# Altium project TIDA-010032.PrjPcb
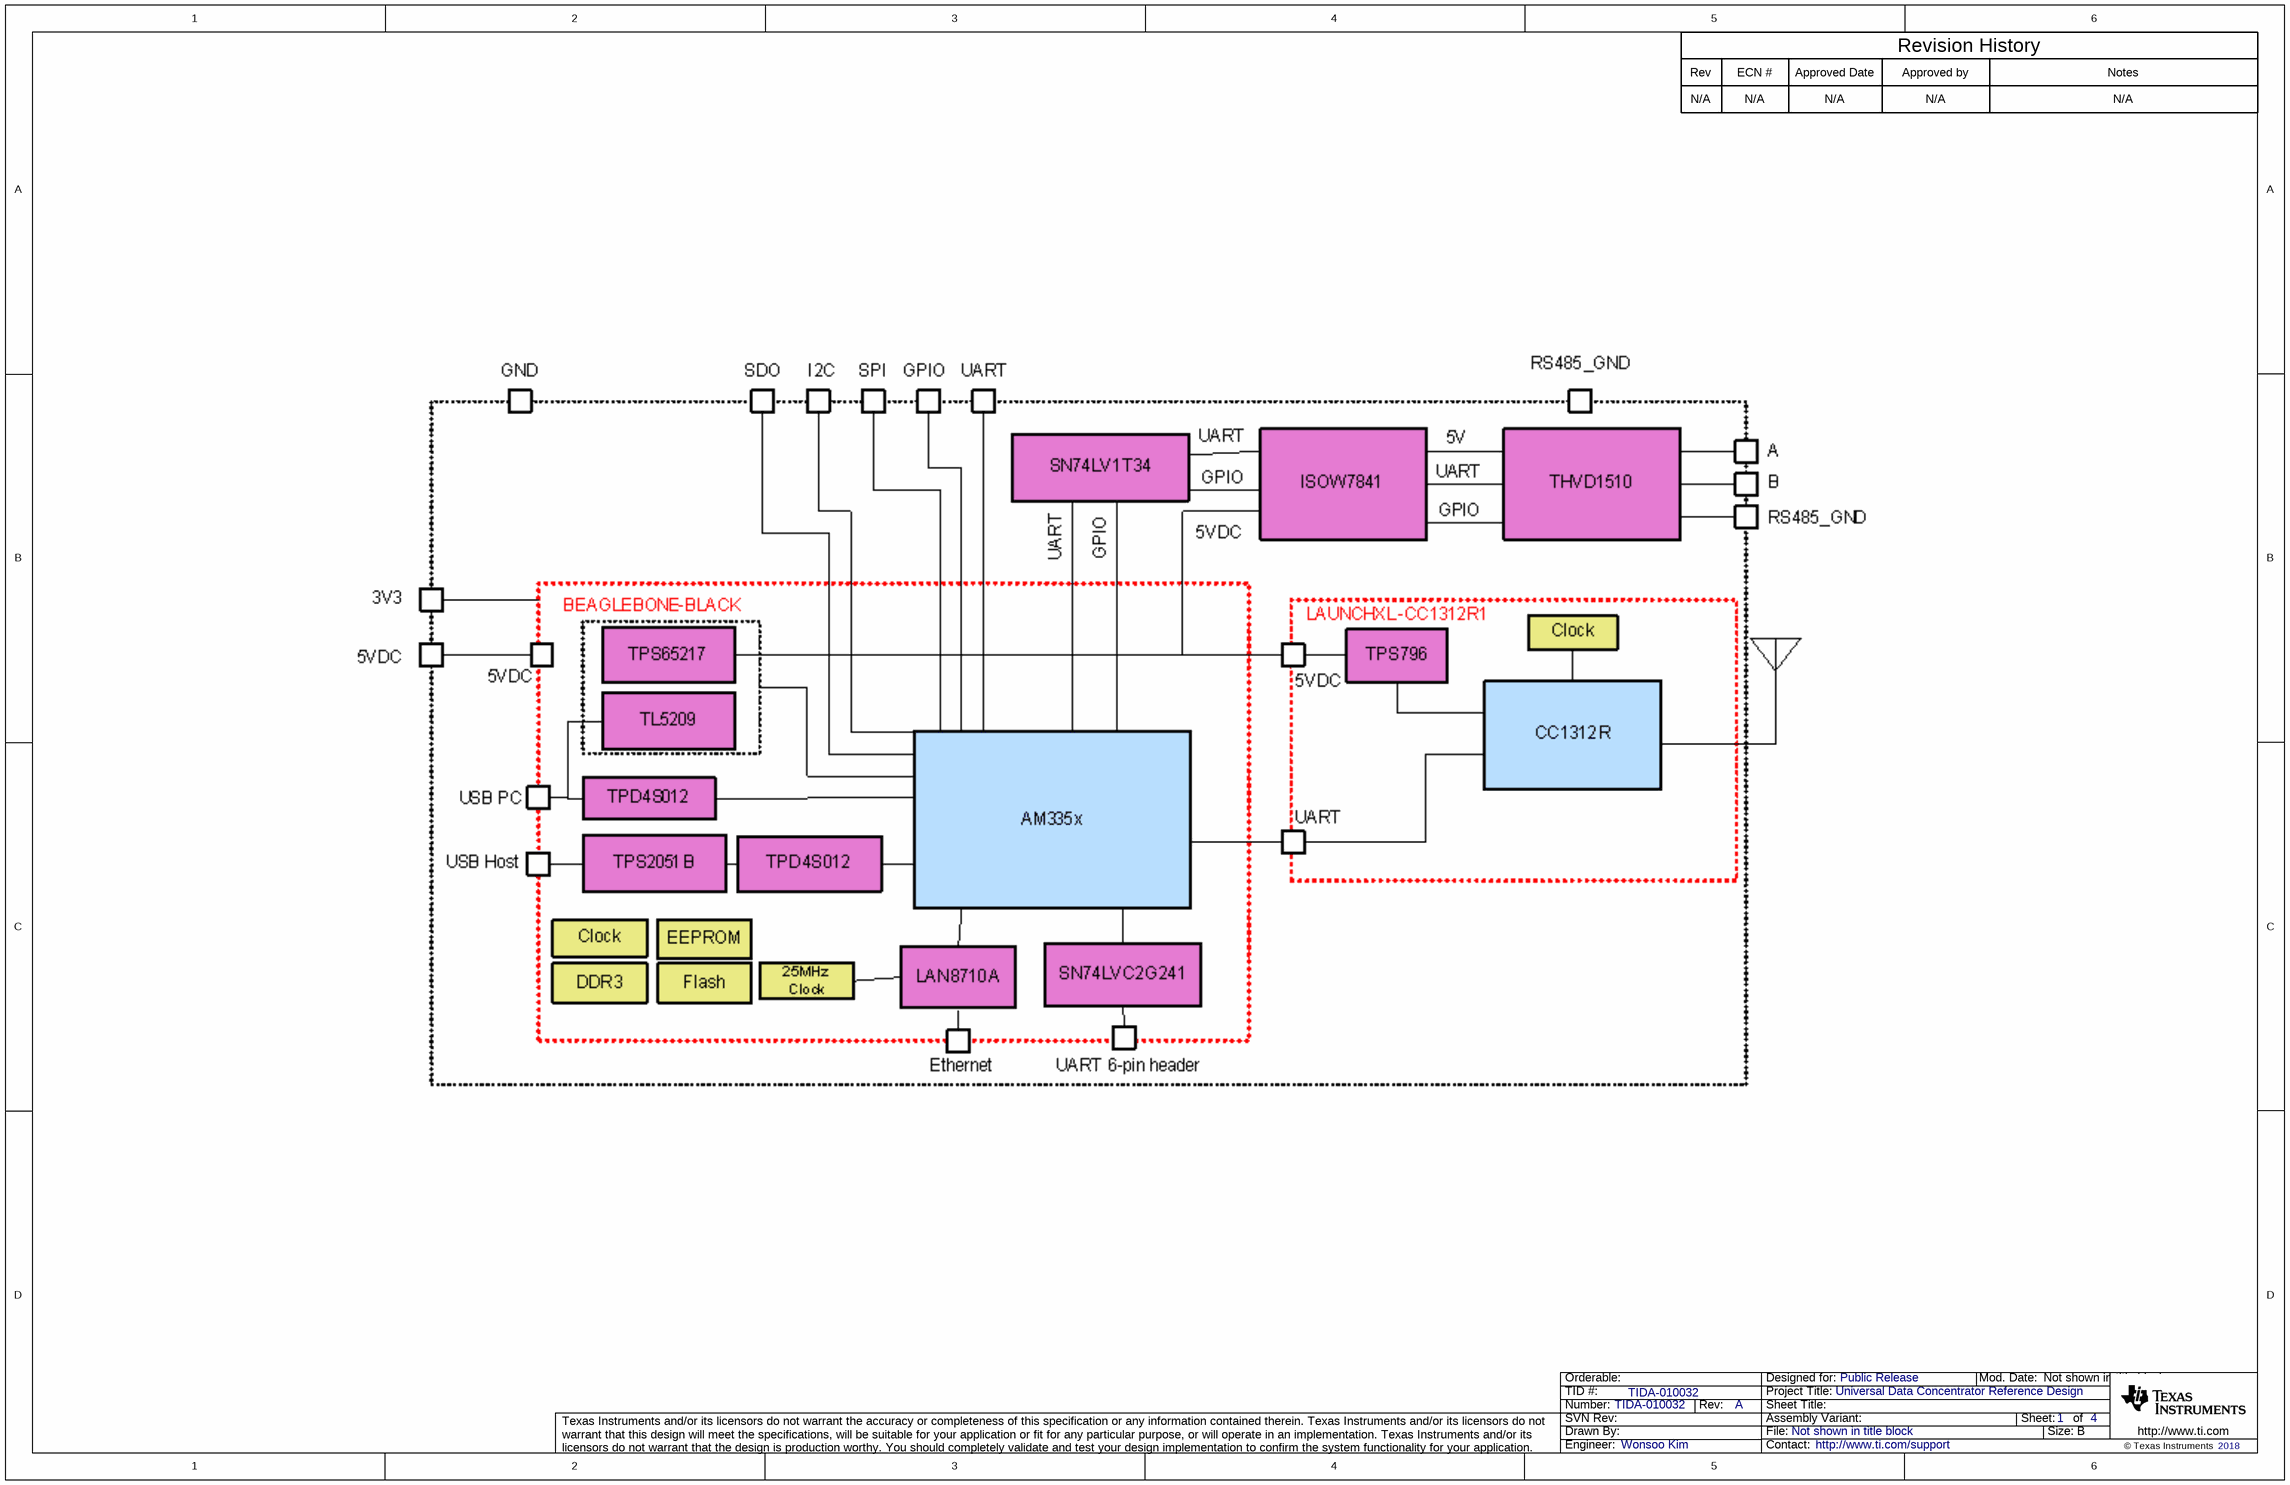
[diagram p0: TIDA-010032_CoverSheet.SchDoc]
CopyrightYear: 2018; PCB_Layout: Wonsoo Kim; PCB_Rev: A; PRJ_Customer: Public Release; PRJ_Engineer: Wonsoo Kim; PRJ_Number: TIDA-010032; PRJ_Title: Universal Data Concentrator Reference Design; SCH_Rev: A; TechSupport: http://www.ti.com/support; TID: TIDA-010032
4 sheets, 62 parts. Net scope: flat (ports and power ports of the same name join across sheets).
Board file: TIDA-010032_PCB.PcbDoc
Sheets:
  TIDA-010032_CoverSheet.SchDoc
  TIDA-010032_1.SchDoc
  TIDA-010032_2.SchDoc
  TIDA-010032_EVM_Hardware.SchDoc

## Sheet TIDA-010032_CoverSheet.SchDoc
size 431 x 279 mm; Date: Not shown in title block; ApprovedBy: Not shown in title block; CheckedBy: Not shown in title block; Author: Not shown in title block; CompanyName: Not shown in title block; Engineer: Not shown in title block; Organization: Not shown in title block; Address1: Not shown in title block; Address2: Not shown in title block; Address3: Not shown in title block; Address4: Not shown in title block; DocumentNumber: 1; Revision: Use project parameter SCH_Rev; SheetNumber: 1; SheetTotal: 4; PageSetup: Record=PageOptions¦CenterHorizontal=True¦CenterVertical=True¦PrintScale=1.00¦XCorrection=1.00¦YCorrection=1.00¦PrintKind=0¦BorderSize=5000000¦LeftOffset=0¦BottomOffset=0¦Orientation=2¦PaperLength=1000¦PaperWidth=1000¦Scale=100¦PaperSource=15¦PrintQuality=600¦MediaType=1¦DitherType=10¦PaperKind=Letter¦PrintScaleMode=1

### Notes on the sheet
- Rev
- N/A
- ECN #
- Approved Date
- Approved by
- Revision History
- Notes

## Sheet TIDA-010032_1.SchDoc
size 431 x 279 mm; Date: Not shown in title block; ApprovedBy: Not shown in title block; CheckedBy: Not shown in title block; Author: Not shown in title block; CompanyName: Not shown in title block; Engineer: Not shown in title block; Organization: Not shown in title block; Address1: Not shown in title block; Address2: Not shown in title block; Address3: Not shown in title block; Address4: Not shown in title block; DocumentNumber: 1; Revision: Use project parameter SCH_Rev; SheetNumber: 2; SheetTotal: 4; PageSetup: Record=PageOptions¦CenterHorizontal=True¦CenterVertical=True¦PrintScale=0.62¦XCorrection=1.00¦YCorrection=1.00¦PrintKind=0¦BorderSize=5000000¦LeftOffset=0¦BottomOffset=0¦Orientation=2¦PaperLength=1000¦PaperWidth=1000¦Scale=100¦PaperSource=15¦PrintQuality=600¦MediaType=1¦DitherType=10¦PrintScaleMode=1¦PaperKind=Letter
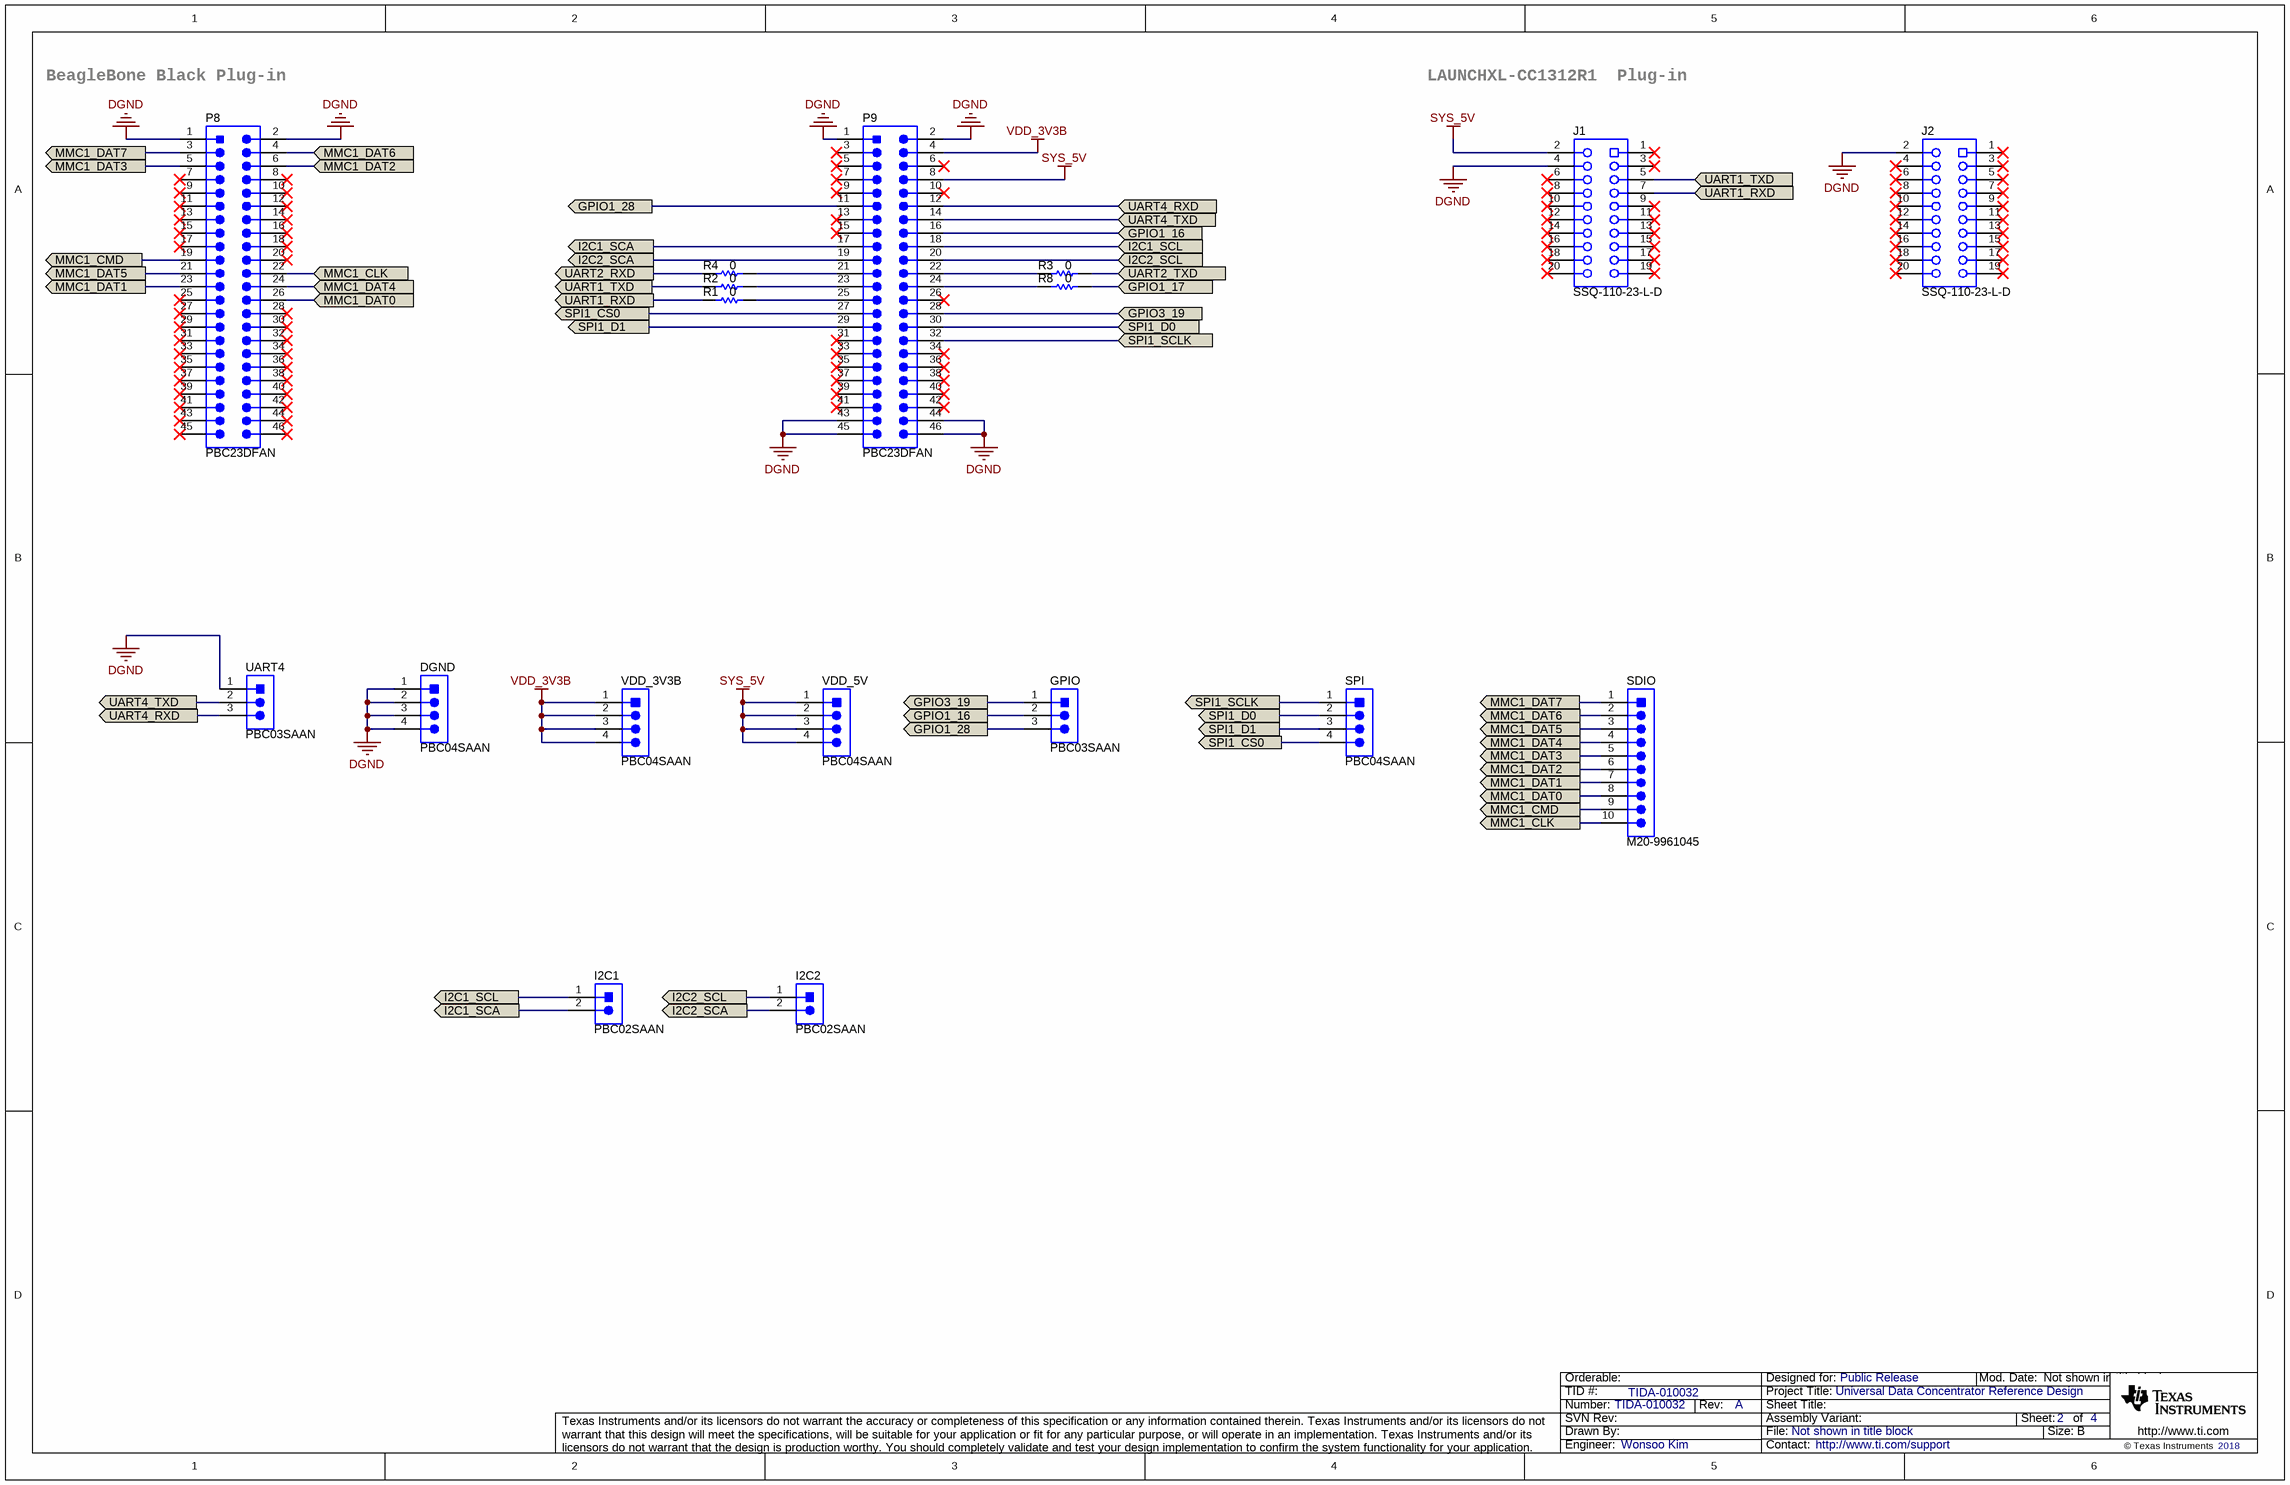
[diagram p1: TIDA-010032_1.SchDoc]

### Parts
DGND  PBC04SAAN  [Sullins_xxC04SAAN]
GPIO  PBC03SAAN  [PBC03SAAN]
I2C1  PBC02SAAN  [Sullins_PBC02SAAN]
I2C2  PBC02SAAN  [Sullins_PBC02SAAN]
J1  SSQ-110-23-L-D  [Samtec_SSQ-110-23-x-D]
J2  SSQ-110-23-L-D  [Samtec_SSQ-110-23-x-D]
P8  PBC23DFAN  [Sullins_PBC23DFAN]
P9  PBC23DFAN  [Sullins_PBC23DFAN]
R1  value 0  [0603]  (hidden comment: ERJ-3GEY0R00V)
R2  value 0  [0603]  (hidden comment: ERJ-3GEY0R00V)
R3  value 0  [0603]  (hidden comment: ERJ-3GEY0R00V)
R4  value 0  [0603]  (hidden comment: ERJ-3GEY0R00V)
R8  value 0  [0603]  (hidden comment: ERJ-3GEY0R00V)
SDIO  M20-9961045  [Harwin_M20-9961045]
SPI  PBC04SAAN  [Sullins_xxC04SAAN]
UART4  PBC03SAAN  [PBC03SAAN]
VDD_3V3B  PBC04SAAN  [Sullins_xxC04SAAN]
VDD_5V  PBC04SAAN  [Sullins_xxC04SAAN]

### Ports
GPIO1_16, GPIO1_17, GPIO1_28, GPIO3_19, I2C1_SCA, I2C1_SCL, I2C2_SCA, I2C2_SCL, MMC1_CLK, MMC1_CMD, MMC1_DAT0, MMC1_DAT1, MMC1_DAT2, MMC1_DAT3, MMC1_DAT4, MMC1_DAT5, MMC1_DAT6, MMC1_DAT7, SPI1_CS0, SPI1_D0, SPI1_D1, SPI1_SCLK, UART1_RXD, UART1_TXD, UART2_RXD, UART2_TXD, UART4_RXD, UART4_TXD

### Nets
DGND: DGND.1 DGND.2 DGND.3 DGND.4 J1.4 J2.2 P8.1 P8.2 P9.1 P9.2 P9.43 P9.44 P9.45 P9.46 UART4.1
SYS_5V: J1.2 P9.8 VDD_5V.1 VDD_5V.2 VDD_5V.3 VDD_5V.4
VDD_3V3B: P9.4 VDD_3V3B.1 VDD_3V3B.2 VDD_3V3B.3 VDD_3V3B.4
GPIO1_16: GPIO.2 P9.16 ; port GPIO1_16
GPIO1_17: R8.2 ; port GPIO1_17
GPIO1_28: GPIO.3 P9.11 ; port GPIO1_28
GPIO3_19: GPIO.1 P9.28 ; port GPIO3_19
I2C1_SCA: I2C1.2 P9.17 ; port I2C1_SCA
I2C1_SCL: I2C1.1 P9.18 ; port I2C1_SCL
I2C2_SCA: I2C2.2 P9.19 ; port I2C2_SCA
I2C2_SCL: I2C2.1 P9.20 ; port I2C2_SCL
MMC1_CLK: P8.22 SDIO.10 ; port MMC1_CLK
MMC1_CMD: P8.19 SDIO.9 ; port MMC1_CMD
MMC1_DAT0: P8.26 SDIO.8 ; port MMC1_DAT0
MMC1_DAT1: P8.23 SDIO.7 ; port MMC1_DAT1
MMC1_DAT2: P8.6 SDIO.6 ; port MMC1_DAT2
MMC1_DAT3: P8.5 SDIO.5 ; port MMC1_DAT3
MMC1_DAT4: P8.24 SDIO.4 ; port MMC1_DAT4
MMC1_DAT5: P8.21 SDIO.3 ; port MMC1_DAT5
MMC1_DAT6: P8.4 SDIO.2 ; port MMC1_DAT6
MMC1_DAT7: P8.3 SDIO.1 ; port MMC1_DAT7
SPI1_CS0: P9.27 SPI.4 ; port SPI1_CS0
SPI1_D0: P9.30 SPI.2 ; port SPI1_D0
SPI1_D1: P9.29 SPI.3 ; port SPI1_D1
SPI1_SCLK: P9.32 SPI.1 ; port SPI1_SCLK
UART1_RXD: J1.7 R1.1 ; port UART1_RXD
UART1_TXD: J1.5 R2.1 ; port UART1_TXD
UART2_RXD: R4.1 ; port UART2_RXD
UART2_TXD: R3.2 ; port UART2_TXD
UART4_RXD: P9.12 UART4.3 ; port UART4_RXD
UART4_TXD: P9.14 UART4.2 ; port UART4_TXD
NetP9_21: P9.21 R4.2
NetP9_22: P9.22 R3.1
NetP9_23: P9.23 R2.2
NetP9_24: P9.24 R8.1
NetP9_25: P9.25 R1.2

Not connected (* = marked no-connect by the designer): J1 1* 3* 6* 8* 9* 10* 11* 12* 13* 14* 15* 16* 17* 18* 19* 20*; J2 1* 3* 4* 5* 6* 7* 8* 9* 10* 11* 12* 13* 14* 15* 16* 17* 18* 19* 20*; P8 7* 8* 9* 10* 11* 12* 13* 14* 15* 16* 17* 18* 20* 25* 27* 28* 29* 30* 31* 32* 33* 34* 35* 36* 37* 38* 39* 40* 41* 42* 43* 44* 45* 46*; P9 3* 5* 6* 7* 9* 10* 13* 15* 26* 31* 33* 34* 35* 36* 37* 38* 39* 40* 41* 42*

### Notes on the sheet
- BeagleBone Black Plug-in
- LAUNCHXL-CC1312R1  Plug-in

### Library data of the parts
DGND SPI VDD_3V3B VDD_5V = CMP-0054583-1: Header, 2.54 mm, 4x1, Gold, TH; Manufacturer: Sullins Connector Solutions; CNHeader: TRUE; Current_A: 3A; Green_Lifecycle: Not Set; Shrouded: N; Gender: Male; Green_REACh: Incomplete; Voltage_V: 1.8kV; Row_Count: 1; Pitch_mm: 2.54; CT: FALSE; Cert_UL: Y
GPIO UART4 = CMP-0002334-1: Header, 100mil, 3x1, Gold, TH; Manufacturer: Sullins Connector Solutions; CNHeader: TRUE; Green_Lifecycle: Not Set; Green_REACh: Incomplete; CT: FALSE
I2C1 I2C2 = CMP-0054566-1: Header, 100mil, 2x1, Gold, TH; Manufacturer: Sullins Connector Solutions; CNHeader: TRUE; Current_A: 3A; Green_Lifecycle: Active; Shrouded: N; Gender: Male; Green_REACh: Passed; Voltage_V: 1.8kV; Row_Count: 1; Pitch_mm: 2.54; CT: FALSE; Cert_UL: Y
J1 J2 = CMP-0055702-1: Receptacle, 2.54mm, 10x2, Gold, TH; Manufacturer: Samtec; CNHeader: FALSE; Current_A: 6.3A; Gender: Female; Cert_CSA: Y; Voltage_V: 550V; CompType: Socket Strip; Row_Count: 2; RowSpacing_mm: 2.54; CT: TRUE
P8 P9 = CMP-0054573-1: Header, 100 mil, 23x2, Gold, TH; Manufacturer: Sullins Connector Solutions; CNHeader: TRUE; Current_A: 3A; Shrouded: N; Gender: Male; Voltage_V: 1.8kV; Row_Count: 2; RowSpacing_mm: 2.54; CT: FALSE; Cert_UL: Y
R1-R4 R8 = CMP-0025874-4: RES, 0, 5%, 0.1 W, AEC-Q200 Grade 0, 0603; Manufacturer: Panasonic; Power_W: 100mW; TempCo: 600 ppm/C; Value_Code: 0000; EIA_Code: E24; SizeX_mm: 1.6; SizeY_mm: 0.8; SizeZ_mm: 1; Value2: 0.1W; SizeArea_mm2: 1.28; CompType: Resistor; AEC Qualified: Y; VDC_V: 50V; AEC Category: Q200; SizeAreaWB_mm2: 4.68
SDIO = CMP-0075170-1: Header, 2.54 mm, 10x1, TH; Manufacturer: Harwin; CNHeader: True; Current_A: 3A; Shrouded: N; Gender: Male; Voltage_V: 750V; Row_Count: 1; Pitch_mm: 2.54; ContactFinish: Gold; CT: False; Cert_UL: Y

## Sheet TIDA-010032_2.SchDoc
size 431 x 279 mm; Date: Not shown in title block; ApprovedBy: Not shown in title block; CheckedBy: Not shown in title block; Author: Not shown in title block; CompanyName: Not shown in title block; Engineer: Not shown in title block; Organization: Not shown in title block; Address1: Not shown in title block; Address2: Not shown in title block; Address3: Not shown in title block; Address4: Not shown in title block; DocumentNumber: 1; Revision: Use project parameter SCH_Rev; SheetNumber: 3; SheetTotal: 4; PageSetup: Record=PageOptions¦CenterHorizontal=True¦CenterVertical=True¦PrintScale=1.00¦XCorrection=1.00¦YCorrection=1.00¦PrintKind=0¦BorderSize=5000000¦LeftOffset=0¦BottomOffset=0¦Orientation=2¦PaperLength=1000¦PaperWidth=1000¦Scale=100¦PaperSource=15¦PrintQuality=600¦MediaType=1¦DitherType=10¦PaperKind=Letter¦PrintScaleMode=1
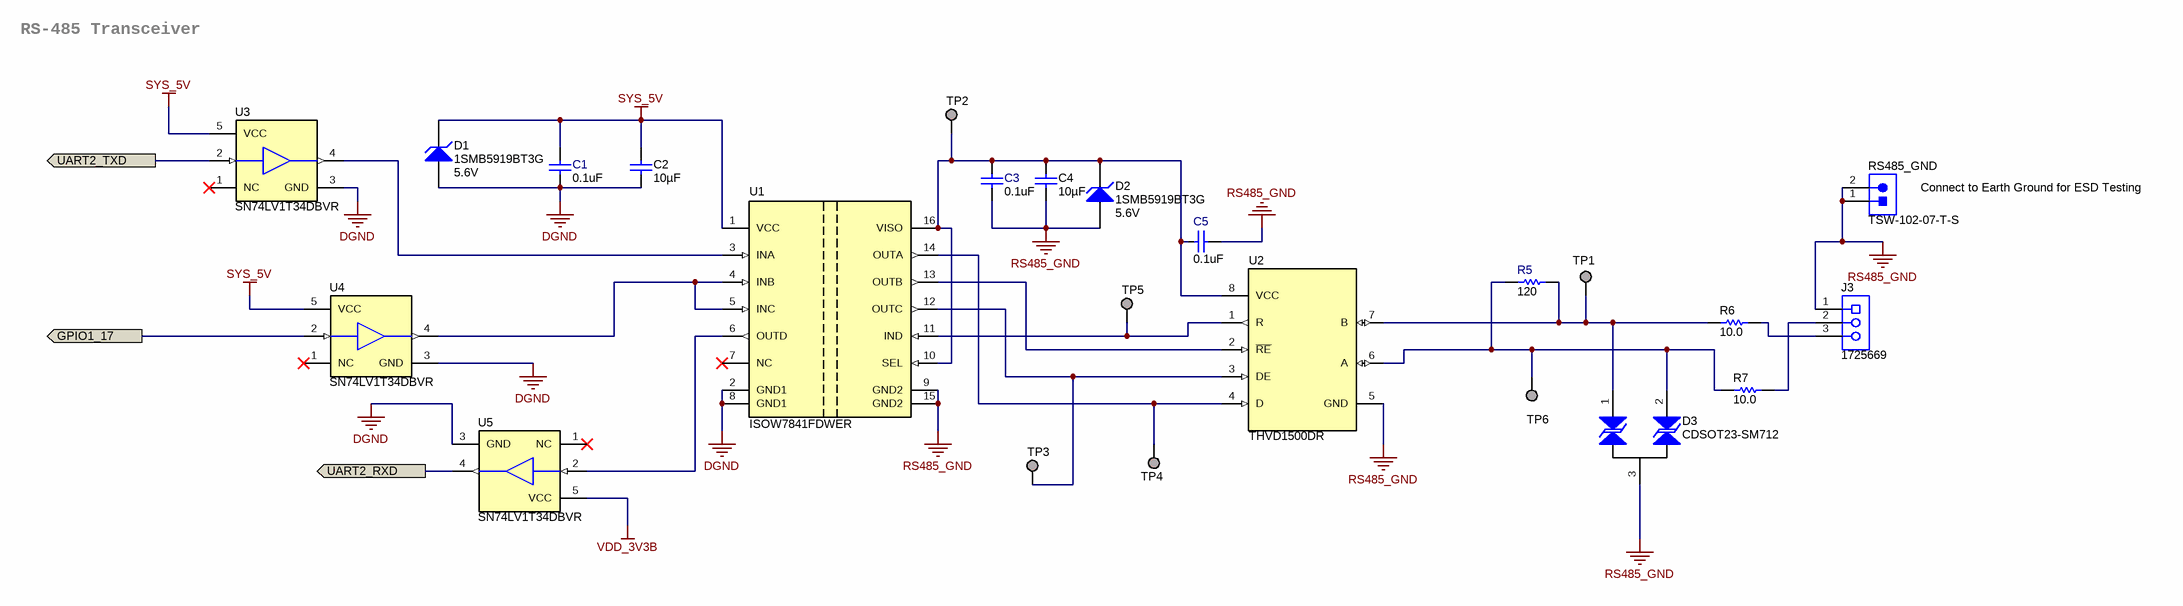
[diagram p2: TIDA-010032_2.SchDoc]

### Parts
C1  value 0.1uF  [0603]  (hidden comment: C0603C104J4RACTU)
C2  ValueDisplayed: 10µF  [0603]  (hidden comment: C0603C106M9PACTU)
C3  value 0.1uF  [0603]  (hidden comment: C0603C104J4RACTU)
C4  ValueDisplayed: 10µF  [0603]  (hidden comment: C0603C106M9PACTU)
C5  value 0.1uF  [0603]  (hidden comment: C0603C104J4RACTU)
D1  1SMB5919BT3G  value 5.6V  [SMB]
D2  1SMB5919BT3G  value 5.6V  [SMB]
D3  CDSOT23-SM712  [SOT-23]
J3  1725669  [Phoenix_1725669]
R5  value 120  [0603]  (hidden comment: CRCW0603120RJNEA)
R6  ValueDisplayed: 10.0  [2512]  (hidden comment: CRCW251210R0FKEG)
R7  ValueDisplayed: 10.0  [2512]  (hidden comment: CRCW251210R0FKEG)
RS485_GND  TSW-102-07-T-S  [Samtec_TSW-102-07-T-S]
TP1  TP_H0.45P0.75  [TP_H045P075]  (value not drawn)  (no BOM)
TP2  TP_H0.45P0.75  [TP_H045P075]  (value not drawn)  (no BOM)
TP3  TP_H0.45P0.75  [TP_H045P075]  (value not drawn)  (no BOM)
TP4  TP_H0.45P0.75  [TP_H045P075]  (value not drawn)  (no BOM)
TP5  TP_H0.45P0.75  [TP_H045P075]  (value not drawn)  (no BOM)
TP6  TP_H0.45P0.75  [TP_H045P075]  (value not drawn)  (no BOM)
U1  ISOW7841FDWER  [DWE0016A]
U2  THVD1500DR  [D0008A_N]
U3  SN74LV1T34DBVR  [DBV0005A_N]
U4  SN74LV1T34DBVR  [DBV0005A_N]
U5  SN74LV1T34DBVR  [DBV0005A_N]

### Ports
GPIO1_17, UART2_RXD, UART2_TXD

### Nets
DGND: C1.2 C2.1 D1.2(A) U1.2(GND1) U1.8(GND1) U3.3(GND) U4.3(GND) U5.3(GND)
RS485_GND: C3.2 C4.1 C5.2 D2.2(A) D3.3 J3.1 RS485_GND.1 RS485_GND.2 U1.9(GND2) U1.15(GND2) U2.5(GND)
SYS_5V: C1.1 C2.2 D1.1(K) U1.1(VCC) U3.5(VCC) U4.5(VCC)
VDD_3V3B: U5.5(VCC)
GPIO1_17: U4.2(A) ; port GPIO1_17
UART2_RXD: U5.4(Y) ; port UART2_RXD
UART2_TXD: U3.2(A) ; port UART2_TXD
NetC3_1: C3.1 C4.2 C5.1 D2.1(K) TP2.1 U1.10(SEL) U1.16(VISO) U2.8(VCC)
NetD3_1: D3.1 R5.1 R6.1 TP1.1 U2.7(B)
NetD3_2: D3.2 R5.2 R7.1 TP6.1 U2.6(A)
NetJ3_2: J3.2 R7.2
NetJ3_3: J3.3 R6.2
NetTP3_1: TP3.1 U1.12(OUTC) U2.3(DE)
NetTP4_1: TP4.1 U1.14(OUTA) U2.4(D)
NetTP5_1: TP5.1 U1.11(IND) U2.1(R)
NetU1_3: U1.3(INA) U3.4(Y)
NetU1_4: U1.4(INB) U1.5(INC) U4.4(Y)
NetU1_6: U1.6(OUTD) U5.2(A)
NetU1_13: U1.13(OUTB) U2.2(~{RE})

Not connected (* = marked no-connect by the designer): U1 7(NC)*; U3 1(NC)*; U4 1(NC)*; U5 1(NC)*

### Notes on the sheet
- RS-485 Transceiver
- (near RS485_GND) Connect to Earth Ground for ESD Testing

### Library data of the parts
C1 C3 C5 = C0603C104J4RACTU: CAP, CERM, 0.1uF, 16V, +/-5%, X7R, 0603; Manufacturer: Kemet; Polarized: N; CompType: Capacitor; ValueDisplayed: 0.1µF; U/M: EA; Cap_F: 0.0000001; Tolerance_%: 5; Value1: Unknown; VDC_V: 16; TaMin_C: -55; TaMax_C: 125
C2 C4 = C0603C106M9PACTU: CAP, CERM, 10 µF, 6.3 V, +/- 20%, X5R, 0603; Manufacturer: Kemet; Polarized: N; CompType: Capacitor; Value: 10uF; U/M: EA; Cap_F: 0.00001; Tolerance_%: 20; ESR_ohm: 0.004; Value1: 0.004 ohm; VDC_V: 6.3; Value2: 6.3V; IRMS_A: 8.9; TaMin_C: -55; TaMax_C: 85; SizeArea_mm2: 1.28; SizeAreaWB_mm2: 4.68; SizeX_mm: 1.6; SizeY_mm: 0.8; SizeZ_mm: 1; AEC Category: Q200
D1 D2 = 1SMB5919BT3G: Diode, Zener, 5.6 V, 550 mW, SMB; Manufacturer: ON Semiconductor; SymbolCreator: a0412235; U/M: EA; Power_W: 0.55; Vz_V: 5.6; Value1: 0.55W; RJA_CperW: 226; SizeAreaWB_mm2: 44.156; SizeArea_mm2: 21.336; SizeY_mm: 3.81; SizeZ_mm: 2.6; AEC Category: Q101
D3 = CMP-0005928-2: Diode, TVS, Bi, 7 V, SOT-23; Manufacturer: Bourns; AEC Category: Q101; SizeX_mm: 2.5; Value: 7V; SizeY_mm: 3; Ppk: 400W; SizeAreaWB_mm2: 14; SizeZ_mm: 1.1; SizeArea_mm2: 7.5
J3 = 1725669: Terminal Block, 3x1, 2.54 mm, TH; Manufacturer: Phoenix Contact; SymbolCreator: a0412235
R5 = CRCW0603120RJNEA: RES, 120 ohm, 5%, 0.1W, 0603; Manufacturer: Vishay-Dale; CompType: Resistor; Value_Code: 120R; Tolerance_%: 5; Power_W: 0.1; VDC_V: 75; TempCo: 200 ppm/C; EIA_Code: E24; U/M: EA
R6 R7 = CRCW251210R0FKEG: RES, 10.0, 1%, 1 W, AEC-Q200 Grade 0, 2512; Manufacturer: Vishay-Dale; CompType: Resistor; Value: 10.0; Res_ohm: 10; Value_Code: 10R0; Tolerance_%: 1; Value2: 1W; VDC_V: 500; TempCo: 100 ppm/C; SizeArea_mm2: 20.16; SizeX_mm: 6.3; SizeY_mm: 3.2; SizeZ_mm: 0.71; EIA_Code: E96; U/M: EA; AEC Category: Q200; AEC Qualified: Y; AEC Grade: 0
RS485_GND = TSW-102-07-T-S: Header, 2.54 mm, 2x1, Tin, TH; Manufacturer: Samtec; SymbolCreator: a0412235; Pitch_mm: 2.54; Gender: Male; Shrouded: N; Row_Count: 1; Current_A: 6.3; Voltage_V: 550; Cert_CSA: Y
TP1-TP6 = CMP-0003719-1: Testpoint; Manufacturer: Texas Instruments; CompType: Pad
U1 = CMP-0082564-1: High-Efficiency, Low-Emissions, Reinforced Digital Isolator With Integrated Power, DWE0016A (SO-MOD-16); Alternate Manufacturer: Texas Instruments; SizeAreaWB_mm2: 151.29; Rating: Catalog; SizeZ_mm: 2.65; SizeX_mm: 10.3; SizeArea_mm2: 106.09; CompType: IC; AEC Qualified: N; AEC Category: Q200
U2 = CMP-0013008-2: 250 kbps RS-485 Transceivers With +/-12-kV IEC ESD Protection, D0008A (SOIC-8); Manufacturer: Texas Instruments; SizeX_mm: 4.9; SizeY_mm: 6.2; CompType: IC; SizeZ_mm: 1.75; SizeArea_mm2: 30.38; SizeAreaWB_mm2: 56.58; U/M: EA
U3-U5 = SN74LV1T34DBVR: Single Power Supply BUFFER Logic Level Shifter (no enable), DBV0005A (SOT-5); Manufacturer: Texas Instruments; SymbolCreator: Altium; SizeArea_mm2: 8.12; SizeAreaWB_mm2: 14.82; SizeX_mm: 2.8; SizeY_mm: 2.9; SizeZ_mm: 1.45; CompType: IC; U/M: EA

## Sheet TIDA-010032_EVM_Hardware.SchDoc
size 431 x 279 mm; Date: Not shown in title block; ApprovedBy: Not shown in title block; CheckedBy: Not shown in title block; Author: Not shown in title block; CompanyName: Not shown in title block; Engineer: Not shown in title block; Organization: Not shown in title block; Address1: Not shown in title block; Address2: Not shown in title block; Address3: Not shown in title block; Address4: Not shown in title block; DocumentNumber: 1; Revision: Use project parameter SCH_Rev; SheetNumber: 4; SheetTotal: 4; PageSetup: Record=PageOptions¦CenterHorizontal=True¦CenterVertical=True¦PrintScale=1.00¦XCorrection=1.00¦YCorrection=1.00¦PrintKind=0¦BorderSize=5000000¦LeftOffset=0¦BottomOffset=0¦Orientation=2¦PaperLength=1000¦PaperWidth=1000¦Scale=100¦PaperSource=15¦PrintQuality=600¦MediaType=1¦DitherType=10¦PaperKind=Letter¦PrintScaleMode=1
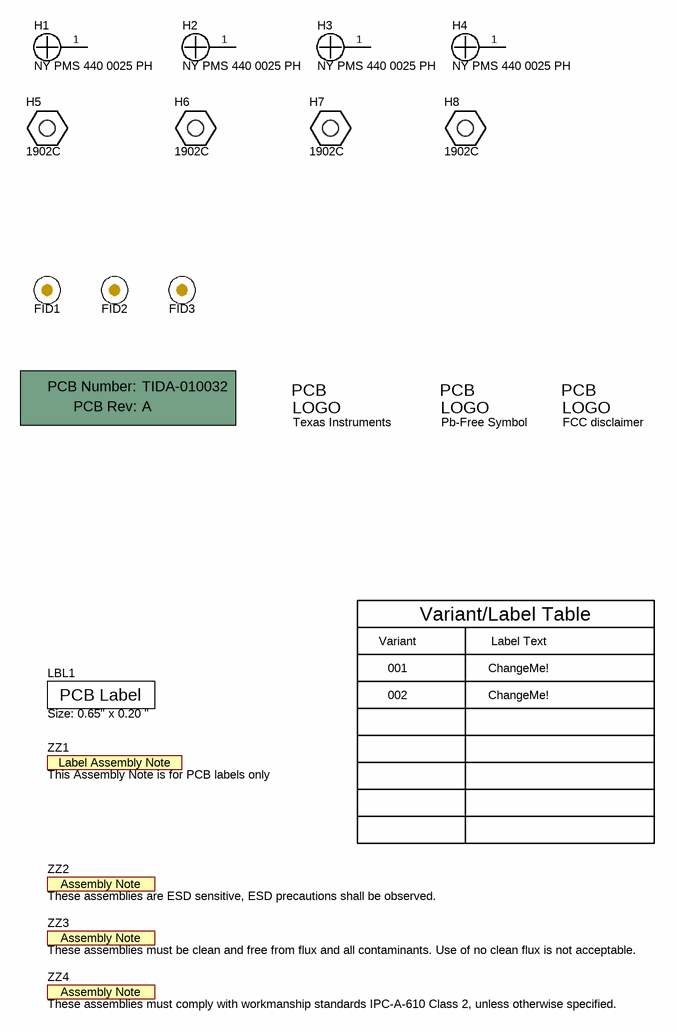
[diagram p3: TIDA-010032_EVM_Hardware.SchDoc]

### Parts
!PCB  Printed Circuit Board  (value not drawn)  (mechanical)
FID1  Fiducial  [Fiducial10-20]  (value not drawn)
FID2  Fiducial  [Fiducial10-20]  (value not drawn)
FID3  Fiducial  [Fiducial10-20]  (value not drawn)
H1  NY PMS 440 0025 PH  [NY PMS 440 0025 PH]
H2  NY PMS 440 0025 PH  [NY PMS 440 0025 PH]
H3  NY PMS 440 0025 PH  [NY PMS 440 0025 PH]
H4  NY PMS 440 0025 PH  [NY PMS 440 0025 PH]
H5  1902C  [Keystone_1902C]
H6  1902C  [Keystone_1902C]
H7  1902C  [Keystone_1902C]
H8  1902C  [Keystone_1902C]
LBL1  Size: 0.65" x 0.20 "  [Label_650x200]
Logo1  Texas Instruments  [TI_Stacked_Overlay_Small]  (no BOM)
Logo2  Pb-Free Symbol  [Pb-Free_Overlay_Small]  (no BOM)
Logo3  FCC disclaimer  [FCC_disclaimer]  (no BOM)
ZZ1  This Assembly Note is for PCB labels only  [AssemblyNoteLabel]  (no BOM)
ZZ2  These assemblies are ESD sensitive, ESD precautions shall be observed.  [AssemblyNote]  (no BOM)
ZZ3  These assemblies must be clean and free from flux and all contaminants. Use of no clean flux is not acceptable.  [AssemblyNote]  (no BOM)
ZZ4  These assemblies must comply with workmanship standards IPC-A-610 Class 2, unless otherwise specified.  [AssemblyNote]  (no BOM)

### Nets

Not connected (* = marked no-connect by the designer): H1 1; H2 1; H3 1; H4 1

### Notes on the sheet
- Variant
- Variant/Label Table
- Label Text
- 001
- 002
- ChangeMe!

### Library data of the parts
!PCB = PCB: Manufacturer: Any; PartNumber: TIDA-010032; SymbolCreator: a0412235
FID1-FID3 = Fiducial: Fiducial mark.  There is nothing to buy or mount.; SymbolCreator: codlsc
H1-H4 = NY PMS 440 0025 PH: Machine Screw, Round, #4-40 x 1/4, Nylon, Philips panhead; Manufacturer: B&F Fastener Supply; CompType: Hardware; SymbolCreator: codlsc; U/M: EA
H5-H8 = 1902C: Standoff, Hex, 0.5"L #4-40 Nylon; Manufacturer: Keystone; CompType: Hardware
LBL1 = THT-14-423-10: Thermal Transfer Printable Labels, 0.650" W x 0.200" H - 10,000 per roll; Manufacturer: Brady; SymbolCreator: a0412235; CompType: Label
Logo1 = TI_Logo: Texas Instrument Corporate Signature; SymbolCreator: codlsc
Logo2 = Pb-Free: SymbolCreator: a0412235
Logo3 = FCC_disclaimer: SymbolCreator: codlsc
ZZ1 = AssemblyNoteLabel: SymbolCreator: a0412235
ZZ2-ZZ4 = AssemblyNote: SymbolCreator: codlsc

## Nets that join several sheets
DGND: TIDA-010032_1 (15 pins), TIDA-010032_2 (8 pins)
SYS_5V: TIDA-010032_1 (6 pins), TIDA-010032_2 (6 pins)
VDD_3V3B: TIDA-010032_1 (5 pins), TIDA-010032_2 (U5.5)
GPIO1_17: TIDA-010032_1 (R8.2), TIDA-010032_2 (U4.2)
UART2_RXD: TIDA-010032_1 (R4.1), TIDA-010032_2 (U5.4)
UART2_TXD: TIDA-010032_1 (R3.2), TIDA-010032_2 (U3.2)

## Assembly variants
001: not fitted FID1 FID2 FID3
